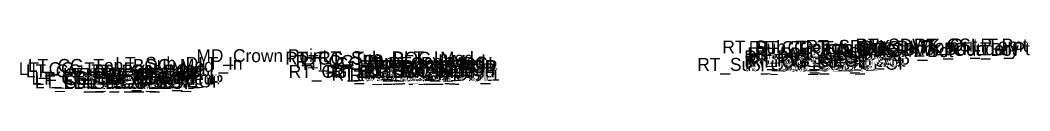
# Model space of a CAD drawing. Extents: x 0 to 6300, y 0 to 9528.
# Drawn here: x 2126 to 2203.9, y 9001.3 to 9005.5 of the extents above; entities that cross this region are included whole.
import ezdxf

# ---------------------------------------------------------------- set-up
doc = ezdxf.new("R2010")
doc.units = 0
doc.layers.add('Default', color=7, linetype='Continuous')

msp = doc.modelspace()

# ---------------------------------------------------------------- texts
at = {"layer": 'Default'}
for s, p in [('RT_Sub_Trench_Out_DLT', (2180.187, 9004.324)), ('RT_CG_Top_Face', (2182.225, 9004.284)), ('RT_CG_Top_BOC', (2182.694, 9004.284)), ('RT_SDWK_In_Top', (2186.62, 9004.374)), ('RT_SDWK_In_Bot', (2186.869, 9004.041)), ('RT_SDWK_Out_Top', (2190.462, 9004.474)), ('RT_SDWK_Out_Bot', (2190.711, 9004.141)), ('Exterior Boundary', (2192.377, 9004.197)), ('RT_CSLP_Pnt', (2194.981, 9004.474)), ('RT_Tie_Pt', (2197.539, 9004.197)), ('MD_Crown Point', (2139.582, 9003.657)), ('RT_CG_Top_BOC_Med', (2146.431, 9003.457)), ('RT_CG_Top_Face_Med', (2147.246, 9003.207)), ('RT_Sub_DLT_In', (2148.986, 9003.499)), ('RT_PV2_OEOT', (2181.873, 9003.562)), ('RT_PV3_OEOT', (2181.873, 9003.312)), ('RT_PV1_OEOT', (2182.112, 9003.812)), ('RT_CG_Bot_IE', (2182.221, 9003.229)), ('RT_CG1_Shelf_Out', (2182.36, 9003.307)), ('RT_CG_Top_Gut', (2182.752, 9003.784)), ('RT_CG_Bot_BOC', (2182.97, 9003.294)), ('LT_CG_Top_Face_Med', (2125.866, 9002.649)), ('LT_CG_Top_Gut_Med', (2126.418, 9002.482)), ('LT_CG_Top_BOC_Med', (2126.569, 9002.899)), ('LT_PV1_PGL', (2131.503, 9002.463)), ('LT_Sub_DLT_In', (2133.327, 9003.059)), ('RT_CG_Bot_BOC_Med', (2146.708, 9002.437)), ('RT_CG_Top_Gut_Med', (2147.8, 9003.04)), ('RT_CG1_Shelf_In', (2149.573, 9002.424)), ('RT_CG_Bot_IE_Med', (2149.976, 9002.476)), ('RT_PV2_OEEOP', (2152.167, 9002.81)), ('RT_PV3_OEEOP', (2152.167, 9002.56)), ('RT_PV2_IEEOP', (2152.928, 9002.81)), ('RT_PV2_PGL', (2154.145, 9002.81)), ('RT_PV1_PGL', (2154.385, 9003.06)), ('RT_Sub_OEOT_CG_1', (2178.247, 9002.979)), ('RT_Sub_OEOT', (2181.92, 9002.937)), ('RT_Sub_OEOP', (2185.155, 9003.063)), ('LT_CG_Bot_BOC_Med', (2126.846, 9001.918)), ('LT_CG_Bot_IE_Med', (2127.094, 9001.879)), ('LT_Sub_IEOT_CG_1', (2127.125, 9001.629)), ('LT_PV2_OEEOP', (2129.285, 9002.213)), ('LT_PV3_OEEOP', (2129.285, 9001.963)), ('LT_Sub_OEEOP', (2129.332, 9001.588)), ('LT_PV2_IEEOP', (2130.046, 9002.213)), ('LT_Sub_IEEOP', (2130.093, 9001.588)), ('LT_CG1_Shelf_In', (2130.711, 9001.931)), ('LT_PV2_PGL', (2131.264, 9002.213)), ('LT_Sub_PGL', (2131.311, 9001.588)), ('LT_Sub_IEOP', (2133.044, 9001.688)), ('RT_Sub_IEOT_CG_1', (2150.007, 9002.226)), ('RT_Sub_IEOP', (2151.405, 9002.167)), ('RT_Sub_OEEOP', (2152.214, 9002.185)), ('RT_Sub_IEEOP', (2152.975, 9002.185)), ('RT_Sub_PGL', (2154.192, 9002.185))]:
    msp.add_text(s, height=1, dxfattribs=at).set_placement(p)

doc.saveas('drawing.dxf')
